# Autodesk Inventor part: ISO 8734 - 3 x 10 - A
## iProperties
IsCustomPart: 0
Created: 2009-02
Part Number: ISO 8734 - 3 x 10 - A
Material: Stahl
Description: Zylinderstift
Document SubType Name: Modeling
Standard: ISO 8734
Designer: UR
Standards Organization: DIN
Language: de-DE
Size Designation: 3 x 10 - A
Categories: <MemberInstance><Categories><Category DisplayName="Verbindungselemente" InternalName="e4da775c-781d-43d5-af7c-5136215cf5a6" Mnemonic="FSTN"><Category DisplayNam
Density: 7.85 g/cm^3
Author: UR
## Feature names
1. Körper [Extrusion]
2. Fase1 [Chamfer]
3. Fase2 [Chamfer]
